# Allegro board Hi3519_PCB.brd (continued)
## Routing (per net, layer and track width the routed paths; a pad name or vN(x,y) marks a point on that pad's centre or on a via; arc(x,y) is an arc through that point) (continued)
AVDD33_AC: length 2.1
  TOP w0.254: v1(93.05,46.89) 93.05,46.89 U3.V18
  BOTTOM w0.254: C23.2 LB9.2 93.39,47.23 v1(93.05,46.89)
AVDD33_PLL: length 2
  TOP w0.254: U3.M5 v1(84.6,50.14)
  BOTTOM w0.254: v1(84.6,50.14) 84.6,50.5 C46.1 84.93,50.62 LB8.1
AVDD33_USB2: length 1.9
  TOP w0.254: U3.G18 92.72,53.71 v1(93.05,53.39)
  BOTTOM w0.254: C777.1 93.05,53.85 v1(93.05,53.39) 92.9,53.24 LB100.1
AVDD33_VDAC: length 1.9
  TOP w0.254: v1(91.75,46.24) 91.75,46.24 92.07,46.56 U3.V17
  BOTTOM w0.254: C48.1 92.17,45.82 v1(91.75,46.24) 91.17,46.24 LB10.1
AVDD_1.05V: length 7.9
  TOP w0.203: v2(127.59,72.33) 127.54,72.33 127.5,72.37 U2.40 ; U2.3 v2(124.56,77.07) ; U2.9 v2(122.16,77.07)
  BOTTOM w0.305: C64.1 122.98,76.37 ; C64.1 121.94,76.37 ; C64.1 122.46,76.89 ; C62.1 123.98,76.89 ; C62.1 124.5,76.37 ; C62.1 123.46,76.37 ; C63.1 129.11,73.18 ; C63.1 128.59,72.66 ; C63.1 129.11,72.14
AVDD_3V3_PHY: length 3.1
  TOP w0.203: U2.6 v2(123.36,77.76) ; v2(126.85,72.91) 126.71,72.77 U2.41
  BOTTOM w0.381: C56.1 126.95,73.01 v2(126.85,72.91)
  vias: v2(123.87,78.46)
AVDD_DDRPLL: length 7.4
  TOP w0.254: U3.E11 v1(88.5,54.69) ; U3.J5 v1(84.6,52.09)
  BOTTOM w0.254: v1(84.6,52.09) 85.18,52.09 LB6.2 85.76,51.51 C801.1 86.03,51.52 86.03,52.85 86.59,53.41 86.59,53.87 86.85,54.12 87.28,54.12 C800.1 87.85,54.69 v1(88.5,54.69)
AVDD_PLL: length 2.1
  TOP w0.254: U3.N8 v1(86.55,49.49)
  BOTTOM w0.254: LB7.1 C45.1 86.61,49.43 v1(86.55,49.49)
DDRIO_1.5V/1.35V: length 92.8
  TOP w0.254: C157.1 76.23,72.15 76.7,71.68 U14.N1 ; U14.C9 84.74,64.28 C162.1 ; U14.H9 80.7,63.26 81.18,62.78 C167.1 ; C164.1 75.16,62.32 76.7,63.86 U14.N9 ; U3.E13 v1(89.15,54.69) U3.E12 ; U14.R1 75.1,71.77 74.59,72.28 74.59,73.25 C166.1 ; U14.A1 C165.1 ; C270.1 86.9,62.88 87.28,63.26 87.28,64.14 U14.A8 ; U3.E6 v1(85.25,54.69) U3.E7 ; C34.1 83.32,64.1 U14.E9
  TOP w0.305: v1(84.3,64.72) U14.D9 ; U14.D2 v1(84.3,70.31) ; U14.G7 81.5,65.91 v1(81.1,65.51) ; U14.R9 75.1,63.53 74.58,63.01 74.07,63.01 73.69,62.63 C163.1 ; U14.B2 85.5,69.91 v1(85.9,69.51) ; U14.F1 v1(81.9,71.11) ; U14.C1 v1(84.3,71.11) ; U14.K2 v1(79.5,70.31) ; U14.H2 v1(81.1,69.51) ; U14.K8 v1(79.5,64.72)
  TOP w0.381: C270.1 87.58,61.76 v2(87.69,61.86) ; C34.1 83.9,61.76 v2(84,61.86) 84.1,61.76 C162.1 ; v2(74.48,61.86) 74.58,61.76 C164.1 ; C167.1 v2(81.84,61.76) ; C225.1 v2(85.63,72.53) ; v2(84.74,74.31) 84.64,74.21 C155.1 R176.2 ; R174.2 C154.1 v2(79.23,60.21) ; C165.1 v2(88.52,69.99) ; C157.1 v2(75.37,73.27) ; v2(72.95,61.86) 73.06,61.76 C163.1 ; C166.1 v2(73.72,73.27)
  BOTTOM w0.254: U14.C9 84.7,61.8 C162.1 ; U14.N1 76.7,71.68 76.23,72.15 C157.1 v2(75.37,73.27) ; C164.1 75.16,62.07 76.7,63.61 U14.N9 ; C271.1 86.64,62.63 86.3,62.97 U15.A1 ; C148.1 89.43,54.97 v1(89.15,54.69) ; v2(82.07,72.4) 80.7,71.03 U15.H9 ; C163.1 73.69,62.31 75.1,63.72 U14.R9 ; U14.R1 75.1,72.39 74.58,72.91 C166.1 ; C101.1 82.71,63.13 82.35,63.49 82.35,64.26 U15.F1
  BOTTOM w0.305: U15.D2 v1(84.3,64.72) ; U14.K8 v1(79.5,64.72) ; v1(81.1,69.51) 81.5,69.12 U15.G7 ; U15.B2 v1(85.9,65.51) ; U15.E9 83.6,71.21 83.6,71.77 83.98,72.15 C174.1 ; U15.H2 v1(81.1,65.51) ; U14.C1 v1(84.3,70.31) ; v2(85.63,72.53) 84.36,71.26 84.36,71.17 v1(84.3,71.11) U15.D9 ; U14.K2 v1(79.5,70.31) ; U15.A8 v1(85.9,69.51)
  BOTTOM w0.381: v2(65.31,63.64) 64.17,63.64 63.91,63.9 R31.2 ; C166.1 v2(73.72,73.27) ; C174.1 v2(84.71,73.27) ; v2(78.21,60.16) R174.2 C160.1 ; C101.1 v2(81.84,61.76) ; v2(74.48,61.86) 74.58,61.76 C164.1 ; C162.1 84.1,61.76 v2(84,61.86) ; v2(72.95,61.86) 73.06,61.76 C163.1 ; v2(82.07,72.4) 82.33,72.66 C168.1 ; C271.1 85.98,61.76 v2(85.91,61.84) ; C225.1 v2(85.63,72.53) ; C158.1 R181.2 v2(79.28,74.74)
  vias: v1(84.66,53.97) v1(84.61,53.39) v2(65.31,64.66) v2(66.45,64.66) v2(66.45,63.64)
DVDD_1.05V: length 5
  TOP w0.203: U2.36 125.36,69.55 v2(125.51,69.41) ; U2.28 122.16,69.57 v2(121.95,69.36)
  BOTTOM w0.305: 122.47,68.62 C60.1 121.95,69.14 ; C61.1 125.39,68.62 ; C61.1 124.87,69.14 ; C61.1 124.35,68.62
GND: length 628
  TOP w0.203: J1.31 v2(60.98,44.2) ; J1.74 v2(56.04,52.6) ; J1.43 v2(60.98,46.6) ; J1.67 v2(60.98,51.4) ; J1.46 v2(56.04,47) ; J1.22 56.24,42.2 56.04,42.4 v2(56.04,42.43) ; J1.37 v2(60.98,45.4) ; J1.13 v2(60.98,40.6) ; J1.61 v2(60.98,50.2) ; J1.55 v2(60.98,49) ; J1.7 v2(60.98,39.4) ; v2(56.04,39.8) J1.10 ; 100.11,46.32 99.93,46.5 97.92,46.5 97.4,47.02 95.85,47.02 v1(95.84,47.03) ; J1.85 v2(60.98,55) ; J1.1 v2(60.98,38.2) ; J1.79 v2(60.98,53.8) ; J1.49 v2(60.98,47.8) ; J1.25 v2(60.98,43) ; J1.28 v2(56.04,43.4) ; J1.52 v2(56.04,48.2) ; J1.40 v2(56.04,45.8) ; J1.62 v2(56.04,50.2) ; J1.19 v2(60.98,41.8) ; J1.34 v2(56.04,44.6) ; J1.73 v2(60.98,52.6)
  TOP w0.254: U3.L5 84.27,51.11 v1(84.6,51.44) U3.K5 ; U3.E4 v1(83.95,55.34) ; v1(96.04,51.83) 95.98,51.76 U3.K22 U3.K21 ; U3.AB22 95.64,43.65 v1(95.66,43.65) ; U3.Y20 v1(94.35,44.94) ; U14.B1 85.5,70.72 v1(85.9,71.12) ; 155.59,51.18 J28.8 v2(152.22,51.18) ; U3.N18 v1(93.05,50.14) ; J28.5 v2(152.22,52.68) ; U3.P21 v1(94.35,48.84) ; v1(91.75,46.89) U3.V16 ; U3.G4 v1(83.95,53.39) ; U3.N2 U3.N1 v1(80.55,49.81) ; v1(96.12,53.63) 96.04,53.71 U3.G22 U3.G21 ; U3.B16 v1(91.75,57.29) ; v1(83.3,49.49) 82.97,49.16 U3.P3 ; U7.13 63.76,26.66 v2(63.53,26.43) ; v1(93.7,53.39) 94.02,53.06 U3.H20 ; U3.K10 v1(87.85,52.09) U3.J11 ; U2.47 125.35,75.17 ; v1(87.85,46.24) 87.52,45.91 U3.W10 87.36,45.75 87.36,45.43 U3.Y10 ; U3.A22 v1(95.65,57.94) ; U22.63 v2(140.98,51.3) ; v1(86.55,54.69) U3.E8 U3.D7 ; U3.AB14 90.12,43.45 v1(90.15,43.42) ; U3.D19 v1(93.7,55.99) 93.37,56.31 U3.C19 ; v1(85.9,46.24) 85.57,45.92 U3.W7 85.45,45.79 85.45,45.39 U3.Y7 ; v1(82,44.29) 81.67,43.97 81.67,43.96 U3.AB1 ; v1(90.78,54.9) 90.76,54.88 90.26,54.88 U3.E14 ; U3.K18 v1(92.4,51.44) ; U3.E10 v1(87.2,54.69) U3.E9 ; U3.W20 v1(93.7,46.24) 93.37,45.92 U3.W19 ; U3.M8 v1(86.55,50.14) 86.87,49.81 U3.N9 ; 155.54,54.18 J28.2 v2(152.22,54.18) ; U3.L9 87.2,51.44 87.52,51.11 U3.L10 v1(87.85,51.44) 88.17,51.11 U3.L11 ; U3.K3 v1(82.65,51.44) ; U3.V8 86.22,46.56 v1(86.55,46.89) ; U3.U2 v1(82.65,47.54) ; v2(152.22,46.68) J28.17 155.59,46.68 ; U3.N5 v1(83.95,50.14) U3.M4 ; U3.B6 84.92,56.96 v1(84.6,57.29) U3.A6 ; v1(88.5,52.09) 88.5,52.09 U3.J12 U3.H12 ; v1(89.8,50.14) U3.M13 ; U3.J10 U3.H9 ; U3.A2 82.32,58.04 v1(82.09,58.28) 81.67,57.87 U3.A1 ; U3.E20 v1(94.35,55.34) ; U3.N14 v1(90.45,50.14) ; U3.B13 U3.A13 89.47,58.08 v1(89.52,58.12) ; U22.43 v2(133.72,48.66) ; U3.R10 v1(87.85,48.19) ; v2(152.22,49.68) J28.11 155.59,49.68 ; U7.36 85.78,26.66 v2(85.88,26.56) ; U3.G19 U3.F20 v1(94.35,54.04) ; U3.V4 v1(83.3,46.24) ; U3.K19 v1(93.7,52.09) ; U14.B3 v1(85.9,68.71) ; U3.K13 v1(89.15,52.09) ; U3.U21 v1(95,46.89) ; U3.N13 v1(89.8,49.49) ; U3.L8 v1(86.55,50.79) ; U22.57 v2(141.25,48.3) ; U3.M20 v1(94.35,50.79) ; v2(64.17,16.27) 64.42,16.53 U20.11 ; U3.C11 v1(88.5,56.64)
  TOP w0.305: C79.1 148.63,41.52 ; C79.1 148.11,41 ; C79.1 147.59,41.52 ; 79.51,79.76 C86.2 ; C86.2 79.51,80.8 ; C86.2 78.99,80.28 ; R50.1 91.82,85.4 ; R50.1 92.34,84.88 ; R50.1 91.3,84.88 ; R137.1 70.66,18.79 ; R137.1 69.61,18.79 ; R137.1 70.13,18.26 ; 105.85,72.27 C53.2 ; C53.2 106.37,72.79 ; C53.2 105.85,73.31 ; R44.1 98.81,85.4 ; R44.1 99.33,84.88 ; R44.1 98.29,84.88 ; U14.D1 v1(83.5,70.31) U14.E2 ; C58.2 106.37,69.79 ; C58.2 105.85,69.27 ; C58.2 105.85,70.31 ; 97.04,84.88 R46.1 ; R46.1 97.56,85.4 ; R46.1 98.08,84.88 ; 134.84,9.29 J4.1 ; J4.1 136.05,8.08 ; J4.1 136.05,10.49 ; J4.1 137.25,9.29 ; 108.85,77.32 C266.2 ; C266.2 109.37,77.84 ; C266.2 108.33,77.84 ; 78.06,52.34 R113.1 78.75,52.95 ; J28.23 162.4,57.43 ; J28.23 160.73,58.51 ; J28.23 160.73,56.35 ; J28.23 159.05,57.43 ; 160.73,41.85 J28.22 ; J28.22 160.73,44.01 ; J28.22 162.4,42.93 ; J28.22 159.05,42.93 ; C163.2 74.21,60.95 ; C163.2 73.17,60.95 ; C163.2 73.69,60.43 ; v2(60.74,23.66) R89.1 61.47,23.14 ; C209.2 132.43,11.88 ; C209.2 131.09,13.22 ; C209.2 131.09,10.55 ; C209.2 129.76,11.88 ; 75.16,60.43 C164.2 74.64,60.95 ; 113.89,25.41 J2.1 ; J2.1 115.09,26.62 ; J2.1 116.3,25.41 ; J2.1 115.09,24.21 ; 153.22,18.48 J16.3 ; J16.3 155.32,17.25 ; J16.3 155.32,19.71 ; J16.3 157.41,18.48 ; v1(85.25,63.77) 85.5,64.02 U14.B9 ; 108.75,73.29 C265.2 ; C265.2 109.28,72.77 ; C265.2 109.28,73.82 ; 68.93,71.77 J5.1 ; J5.1 71.34,71.77 ; J5.1 70.13,70.56 ; J5.1 70.13,72.98 ; 77.2,60.43 R175.1 ; 146.97,41 R68.1 ; R68.1 146.45,41.52 ; R68.1 147.49,41.52 ; 105.85,68.89 C40.2 106.37,68.37 ; U14.F9 v1(81.9,63.92) U14.G9 ; C35.2 61.6,73.94 ; C35.2 61.08,73.42 ; C35.2 61.6,72.9 ; C246.2 106.37,76.79 ; C246.2 105.85,77.31 ; C246.2 105.85,76.27 ; 90.68,24 C38.2 ; C38.2 90.68,25.05 ; C38.2 90.16,24.53 ; 97.76,8.4 J25.4 ; J25.4 98.46,9.29 ; J25.4 97.76,10.18 ; J3.1 57.88,25.03 ; J3.1 56.67,26.24 ; J3.1 56.67,23.83 ; J3.1 55.47,25.03 ; 75.71,74.08 C157.2 ; C157.2 76.75,74.08 ; C157.2 76.23,74.6 ; U14.D8 v1(83.5,64.71) U14.E8 ; 77.65,79.76 R182.2 ; R182.2 78.17,80.28 ; R182.2 77.65,80.8 ; 154.07,80.09 J20.11 155.47,81.49 ; 134.51,43.55 C71.2 ; C71.2 135.03,43.03 ; C71.2 135.55,43.55 ; C2.2 74.07,56.44 ; C2.2 73.55,55.92 ; C2.2 74.59,55.92 ; C47.2 97.02,41.42 ; 74.07,52.81 C3.2 73.55,53.33 ; 108.33,68.37 C24.2 ; C24.2 108.85,68.89 ; C24.2 109.37,68.37 ; 101.38,8.4 J50.1 ; J50.1 100.68,9.29 ; J50.1 101.38,10.18 ; C193.1 v2(100.23,42.94) ; U14.T9 v1(74.3,63.77) ; 86.89,10.43 J21.8 86.89,8.65 ; 94.54,84.88 R42.1 ; R42.1 95.06,85.4 ; R42.1 95.58,84.88 ; U14.T1 v1(74.3,71.32) ; R47.1 88.59,84.88 ; R47.1 87.55,84.88 ; R47.1 88.07,85.4 ; 88.8,84.88 R48.1 ; R48.1 89.84,84.88 ; R48.1 89.32,85.4 ; C165.2 89.34,71.24 ; C165.2 89.86,70.71 ; C165.2 89.34,70.19 ; 102.18,53.35 R94.2 101.66,53.88 ; J26.1 66.01,84.09 ; J26.1 65.31,84.98 ; J26.1 65.31,83.2 ; C190.1 v2(100.23,43.96) ; C219.2 75.23,51.22 ; C219.2 74.71,51.74 ; C219.2 74.19,51.22 ; R177.1 81.82,74.73 ; 154.07,63.96 J20.12 155.47,62.56 ; 80.24,60.43 R114.1 ; U14.M1 77.25,70.97 v1(77.25,71.26) ; 80.8,74.73 C156.2 80.28,74.21 ; v1(86.77,63.9) 86.72,63.9 U14.A9 ; 96.54,36.96 R98.1 97.06,37.48 ; 152.8,57.43 J28.21 ; J28.21 154.77,58.51 ; J28.21 154.77,56.35 ; J28.21 156.73,57.43 ; 154.77,41.85 J28.20 ; J28.20 156.73,42.93 ; J28.20 154.77,44.01 ; J28.20 152.8,42.93 ; U14.G1 81.5,70.71 v1(81.9,70.32) ; C166.2 74.58,74.6 ; C166.2 75.1,74.08 ; C166.2 74.06,74.08 ; 158.22,11.36 J16.1 ; J16.1 156.98,13.58 ; J16.1 158.22,15.8 ; R49.1 91.09,84.88 ; R49.1 90.57,85.4 ; R49.1 90.05,84.88 ; R45.1 96.83,84.88 ; R45.1 95.79,84.88 ; R45.1 96.31,85.4 ; 81.7,60.95 C167.2 81.18,60.43 ; U14.E1 v1(82.7,71.11) ; U14.J8 v1(80.3,65.51) ; U14.J2 v1(80.3,70.32) ; C235.2 105.85,78.64 ; C235.2 106.37,78.12 ; C235.2 105.85,77.6 ; U14.P1 v1(75.9,71.31) ; U14.M9 v1(77.9,63.92) ; U14.P9 v1(75.9,63.77) ; 76.18,60.43 C153.2 ; U14.G8 v1(81.9,64.72)
  TOP w0.356: v2(146.59,49.85) 146.64,49.8 U12.3 U12.8 v2(149.53,49.8) ; v2(149.53,52.97) U11.8 U11.3 v2(146.59,52.97) ; R245.1 v2(89.62,18.81) ; v2(110.99,15.73) 110.92,15.8 U23.4 ; R81.2 v2(115.19,15.79)
  TOP w0.381: OSC1.2 131.35,66.18 v2(130.71,66.82) ; R143.2 125.79,67.88 v2(125.86,67.81) ; C4.2 138.8,42.88 v2(138.84,42.84) ; U16.10 v2(71.38,23.76) ; C213.2 v2(118.78,68.98) ; U13.1 v2(93.31,31.57) ; C227.2 v2(93.31,33.92) ; C270.2 v2(87.69,60.95) ; J12.11 148.53,38.08 v2(148.24,38.37) ; v2(143.67,27.32) 143.79,27.32 144.43,27.95 C247.2 ; J16.1 159.65,13.58 ; C155.2 83.85,73.04 v2(83.34,72.53) ; R38.2 v2(141.64,44.06) ; R151.2 v2(141.76,57.67) ; C154.2 v2(79.23,62.55) ; Q3.2 v2(139.35,25.54) ; C225.2 v2(85.63,75.71) ; 130.33,69.48 v2(130.33,70.37) ; X1.2 73.65,51.53 v2(74.33,52.21) ; C83.2 147.25,28.44 v2(147.6,28.08) ; J12.10 v2(150.12,22.14) ; U17.2 v2(147.99,45.1) ; X1.4 v2(70.6,49.33) ; R141.2 117.86,78.45 v2(117.85,78.46) ; R214.2 142.93,48.27 v2(143.21,48.27) ; R70.2 143.16,27.95 v2(142.65,27.45) ; C124.1 v2(61.94,19.57) ; C162.2 v2(83.98,60.95) C34.2 ; v2(96.42,42.18) 96.58,42.03 C47.2 ; R91.2 v2(98.07,38.75) ; R35.2 v2(144.05,57.67) ; J12.6 v2(151.03,27.98) ; R39.2 v2(145.19,57.67) ; C65.2 v2(126.88,70.17) ; v2(98.28,40.15) C228.2 ; v2(157.89,38.98) J12.13 v2(161.55,38.98) ; R55.2 v2(143.95,23.51) ; v2(77.42,47.11) 77.53,47 R93.2 ; U13.3 v2(93.18,29.67)
  TOP w0.508: J18.12 121.6,58.6 v2(121.25,58.24) ; v2(120.07,60.45) 119.82,60.2 J18.7 ; J18.72 v2(120.55,34.6) ; J18.68 v2(120.55,36.2) ; J18.76 v2(120.55,33) ; J18.80 v2(120.55,31.4)
  GND02 w0.305: 158.22,11.36 J16.1 ; J16.1 159.45,13.58 ; J16.1 156.98,13.58 ; J16.1 158.22,15.8 ; J25.4 97.76,10.18 ; J25.4 98.46,9.29 ; J25.4 97.76,8.4 ; 134.84,9.29 J4.1 ; J4.1 137.25,9.29 ; J4.1 136.05,10.49 ; J4.1 136.05,8.08 ; J50.1 101.38,10.18 ; J50.1 101.38,8.4 ; J50.1 100.68,9.29 ; 160.73,41.85 J28.22 ; J28.22 160.73,44.01 ; J28.22 162.4,42.93 ; J28.22 159.05,42.93 ; 129.76,11.88 C209.2 ; C209.2 131.09,10.55 ; C209.2 132.43,11.88 ; C209.2 131.09,13.22 ; 152.8,57.43 J28.21 ; J28.21 154.77,56.35 ; J28.21 156.73,57.43 ; J28.21 154.77,58.51 ; J28.23 160.73,58.51 ; J28.23 160.73,56.35 ; J28.23 159.05,57.43 ; J28.23 162.4,57.43 ; 152.8,42.93 J28.20 ; J28.20 156.73,42.93 ; J28.20 154.77,44.01 ; J28.20 154.77,41.85 ; 154.07,80.09 J20.11 155.47,81.49 ; J5.1 71.34,71.77 ; J5.1 70.13,70.56 ; J5.1 70.13,72.98 ; J5.1 68.93,71.77 ; 153.22,18.48 J16.3 ; J16.3 157.41,18.48 ; J16.3 155.32,19.71 ; J16.3 155.32,17.25 ; J21.8 87.58,9.54 ; J21.8 86.89,10.43 ; J21.8 86.89,8.65 ; 154.07,63.96 J20.12 155.47,62.56 ; 113.89,25.41 J2.1 ; J2.1 115.09,26.62 ; J2.1 116.3,25.41 ; J2.1 115.09,24.21 ; 56.67,23.83 J3.1 ; J3.1 56.67,26.24 ; J3.1 57.88,25.03 ; J3.1 55.47,25.03 ; J26.1 66.01,84.09 ; J26.1 65.31,83.2 ; J26.1 65.31,84.98
  ART03 w0.762: J20.13 149.75,78.89 146.21,82.44
  BOTTOM w0.254: C42.2 92.14,52.78 v1(92.23,52.69) 92.23,52.19 C41.2 ; C23.1 95.33,47.54 v1(95.84,47.03) ; U10.24 107.35,77.62 107.22,77.48 ; U10.49 109.35,68.24 109.12,68.47 ; v1(96.04,55.01) 95.41,54.37 R34.1 ; C39.2 83.46,52.9 v1(83.95,53.39) ; 109.12,77.36 109.35,77.58 U10.28 ; v1(87.2,48.84) 86.48,48.84 C189.2 ; U10.13 105.99,74.29 ; v1(91.75,46.89) 91.87,46.76 C48.2 ; C176.2 85.07,47.07 v1(84.6,47.54) 84.89,47.84 C20.2 ; U10.21 105.85,77.58 106.08,77.36 ; U10.44 109.21,70.29 ; U10.16 105.99,75.79 ; v1(88.5,55.34) 88.23,55.61 C800.2 ; C45.2 88.08,49.07 v1(87.85,48.84) ; v1(94.35,54.04) 94.3,54.09 C777.2 ; C145.2 85.86,55.38 v1(86.55,54.69) 86.55,54.38 86.13,53.96 C146.2 ; v1(83.95,50.14) 83.89,50.2 C46.2 ; U10.9 105.99,72.29 ; C147.2 84.06,55.45 v1(83.95,55.34) ; 106.08,68.59 105.77,68.29 U10.1 ; U10.53 107.35,68.43 ; R558.1 89.46,58.07 v1(89.52,58.12) ; U10.39 109.21,72.79 ; v1(88.5,51.44) 88.59,51.35 C188.2 ; U10.6 105.99,70.79 ; v1(86.55,52.09) 86.55,51.95 C801.2 ; v1(90.34,54.4) 89.97,54.03 C148.2 ; U10.55 106.35,68.43 ; U10.33 109.26,75.79
  BOTTOM w0.305: 149.75,49.82 C109.2 ; C109.2 150.27,50.35 ; C109.2 150.79,49.82 ; U14.M9 v1(77.9,63.92) ; U14.G1 81.5,70.71 v1(81.9,70.32) U15.G8 ; J25.4 98.46,9.29 ; J25.4 97.76,8.4 ; J25.4 97.76,10.18 ; C105.2 131.5,41.3 ; C105.2 131.5,40.26 ; C105.2 132.02,40.78 ; 158.22,11.36 J16.1 ; J16.1 156.98,13.58 ; J16.1 158.22,15.8 ; J16.1 159.45,13.58 ; C91.2 122.05,57.31 ; C91.2 122.05,56.26 ; C91.2 121.53,56.78 ; C76.2 131.6,49.08 ; C76.2 132.12,48.55 ; C76.2 131.08,48.55 ; 122.47,67.81 C60.2 121.95,67.29 ; 87.6,46.84 C177.2 86.6,46.84 v1(86.55,46.89) ; 56.67,23.83 J3.1 ; J3.1 57.88,25.03 ; J3.1 56.67,26.24 ; J3.1 55.47,25.03 ; J21.8 87.58,9.54 ; J21.8 86.89,10.43 ; J21.8 86.89,8.65 ; 137.05,53.71 C75.2 ; C75.2 138.09,53.71 ; C75.2 137.57,53.19 ; 121.21,75.19 C55.2 121.74,75.71 ; 99.2,27.68 C36.2 ; C36.2 100.25,27.68 ; C36.2 99.73,27.15 ; U14.E2 v1(83.5,70.31) U15.D8 ; 139.07,49.79 C68.2 ; C68.2 138.55,50.31 ; C68.2 139.07,50.83 ; U14.T1 v1(74.3,71.32) ; 73.69,60.43 C163.2 ; C163.2 73.17,60.95 ; C163.2 74.21,60.95 ; 82.21,51.17 C44.2 81.82,50.73 ; 83.98,74.6 C174.2 83.46,74.08 ; 81.3,84.88 R109.2 81.82,85.4 ; v1(85.25,63.77) 85.5,64.02 U14.B9 ; 120.83,71.88 C59.2 ; C59.2 121.35,72.4 ; C59.2 120.83,72.93 ; 130.56,61.09 C77.2 ; C77.2 131.08,61.61 ; C77.2 130.56,62.13 ; J2.1 116.3,25.41 ; J2.1 115.09,24.21 ; J2.1 115.09,26.62 ; J2.1 113.89,25.41 ; C78.2 135.93,44.13 ; C78.2 135.41,43.61 ; C78.2 134.89,44.13 ; 155.47,81.49 J20.11 154.07,80.09 ; C66.2 136.21,76.5 ; C66.2 135.69,77.02 ; C66.2 135.69,75.98 ; 74.06,74.08 C166.2 ; C166.2 75.1,74.08 ; C166.2 74.58,74.6 ; C118.2 126.9,47.04 ; C118.2 126.38,46.52 ; C118.2 127.42,46.52 ; U14.J2 v1(80.3,70.32) ; 124.45,71.64 C57.2 124.97,72.16 ; 119.96,51.96 C92.2 119.44,51.44 ; 159.05,57.43 J28.23 ; J28.23 160.73,56.35 ; J28.23 160.73,58.51 ; J28.23 162.4,57.43 ; J28.21 156.73,57.43 ; J28.21 154.77,58.51 ; J28.21 154.77,56.35 ; J28.21 152.8,57.43 ; 75.16,60.43 C164.2 ; C164.2 74.64,60.95 ; C164.2 75.68,60.95 ; 88.57,46.88 C151.2 ; C151.2 88.97,47.32 ; C151.2 88.97,46.43 ; C88.2 61.98,24.12 ; C88.2 61.98,23.08 ; C88.2 61.45,23.6 ; 100.68,9.29 J50.1 ; J50.1 101.38,10.18 ; J50.1 101.38,8.4 ; J5.1 71.34,71.77 ; J5.1 70.13,72.98 ; J5.1 68.93,71.77 ; J5.1 70.13,70.56 ; 94.54,49 R92.2 94.99,49.44 ; U15.E1 v1(83.5,64.71) ; v1(83.5,64.71) U15.D1 ; v1(83.5,64.71) U14.E8 ; 61.19,70.23 C13.2 ; C13.2 60.67,70.75 ; C13.2 61.19,71.28 ; 84.47,26.66 C50.2 ; C50.2 85.51,26.66 ; C50.2 84.99,26.14 ; U14.J8 v1(80.3,65.51) ; C52.2 79.95,32.65 ; C52.2 79.43,33.18 ; C52.2 79.43,32.13 ; U15.A9 86.3,70.72 v1(85.9,71.12) 85.5,70.72 U14.B1 ; U15.F9 v1(82.7,71.11) ; 88.97,47.52 C22.2 88.57,47.97 ; 136.29,48.55 C69.2 ; C69.2 136.81,49.08 ; C69.2 137.33,48.55 ; R168.2 69.44,84.85 ; R168.2 68.92,84.33 ; R168.2 68.92,85.37 ; 111.1,30.48 C14.2 ; C14.2 111.63,31 ; C14.2 111.1,31.52 ; R180.1 78.26,74.6 ; 83.01,46.88 C150.2 83.41,46.43 ; 128.4,47.63 C106.2 ; C106.2 127.88,48.15 ; C106.2 128.4,48.67 ; C67.2 139.07,53.32 ; C67.2 138.55,52.8 ; C67.2 139.07,52.28 ; C64.2 122.98,75.55 ; C64.2 122.46,75.03 ; C64.2 121.94,75.55 ; 75.71,74.08 C157.2 76.23,74.6 ; 160.73,41.85 J28.22 ; J28.22 159.05,42.93 ; J28.22 162.4,42.93 ; J28.22 160.73,44.01 ; 131.09,10.55 C209.2 ; C209.2 129.76,11.88 ; C209.2 131.09,13.22 ; C209.2 132.43,11.88 ; 86.12,26.66 C51.2 ; C51.2 87.17,26.66 ; C51.2 86.64,26.14 ; 82.33,74.6 C168.2 82.85,74.08 ; C19.2 88.35,47.61 ; C19.2 87.95,47.16 ; C19.2 87.95,48.06 ; 93.82,54.69 C149.2 ; C149.2 93.82,55.58 ; C149.2 94.22,55.13 ; 154.77,41.85 J28.20 ; J28.20 154.77,44.01 ; J28.20 156.73,42.93 ; J28.20 152.8,42.93 ; C80.2 139.58,43.34 ; C80.2 139.58,42.29 ; C80.2 139.06,42.81 ; 110.23,49.54 C37.2 110.75,49.02 ; 83.38,49.23 C175.2 82.98,48.78 ; C74.2 134.28,53.71 ; C74.2 133.76,53.19 ; C74.2 133.24,53.71 ; J16.3 155.32,19.71 ; J16.3 153.22,18.48 ; J16.3 157.41,18.48 ; J16.3 155.32,17.25 ; 104.3,44.1 C16.2 ; C16.2 103.78,44.62 ; C16.2 104.82,44.62 ; 91.81,11.19 C81.2 ; C81.2 92.33,10.67 ; C81.2 92.33,11.71 ; 94.34,51.45 C152.2 93.95,51.9 ; 124.35,67.81 C61.2 124.87,67.29 ; 155.47,62.56 J20.12 154.07,63.96 ; U14.T9 v1(74.3,63.77) ; 95.56,26.93 C17.2 ; C17.2 95.56,27.97 ; C17.2 96.08,27.45 ; C159.2 77.25,74.6 ; 74.94,9.02 C82.2 ; C82.2 74.94,10.06 ; C82.2 74.41,9.54 ; 132.99,38.75 R56.2 ; R56.2 133.51,39.27 ; R56.2 134.03,38.75 ; U15.B3 v1(85.9,66.32) ; U14.P1 v1(75.9,71.31) ; 133.25,43.61 C70.2 132.73,44.13 ; 74.29,30.24 C212.1 ; C212.1 74.81,30.76 ; C212.1 74.81,29.72 ; J4.1 136.05,10.49 ; J4.1 136.05,8.08 ; J4.1 137.25,9.29 ; J4.1 134.84,9.29 ; 123.98,75.03 C62.2 ; C62.2 124.5,75.55 ; C62.2 123.46,75.55 ; U14.M1 77.25,70.97 v1(77.25,71.26) ; U14.P9 v1(75.9,63.77) ; R115.1 81.31,74.6 ; C90.2 57.45,59.1 ; C90.2 56.93,59.62 ; C90.2 56.41,59.1 ; 119.96,52.97 C89.2 119.44,53.5 ; C72.2 138.21,59.87 ; U14.G9 v1(81.9,64.72)
  BOTTOM w0.356: R103.1 v2(122.23,26.28)
  BOTTOM w0.381: v2(151.27,38.98) J13.10 150.12,40.1 v2(150.22,40.2) ; C233.2 v2(127.16,77.99) ; C73.2 v2(128.17,52.97) ; v2(147.83,34.13) 147.83,33.87 147.4,33.44 C84.2 ; R108.2 v2(72.42,81.29) ; v2(77.63,62.5) 77.2,62.07 C160.2 ; v2(81.84,60.9) 81.89,60.95 C101.2 ; R244.2 v2(68.99,13.35) ; v2(157.89,38.98) J12.13 v2(161.55,38.98) ; C242.2 127.28,55.77 v2(127.18,55.67) ; R243.2 v2(60.48,13.35) ; C15.2 v2(111.03,43.07) ; R253.1 v2(65.31,74.18) ; C1.2 v2(80.32,75.99) ; R252.2 v2(129.19,71.01) ; C271.2 v2(85.91,60.95) ; v2(105.06,46.5) 105.31,46.75 R12.2 ; J13.11 v2(151.27,24.38) ; R167.2 v2(66.83,79.14) ; C237.2 126.33,67.39 125.91,67.81 v2(125.86,67.81) ; C229.2 63.85,26.11 v2(63.53,26.43) ; R71.2 143.29,33.44 143.5,33.23 v2(143.67,33.23) 144.06,33.23 C248.2 ; C158.2 v1(80.29,72.53) ; 85.88,82.56 v2(85.88,83.33) ; C221.2 v2(69.37,80.91) ; C56.2 v2(127.54,74.56) ; 83.85,82.56 v2(83.85,83.33) R40.2 ; v2(80.22,59.83) 80.24,59.86 R114.1 R178.1 ; R232.2 v2(107.56,30.83) ; v2(161.68,23.48) J12.9 157.93,23.48 v2(157.9,23.51) ; R187.1 v2(66.71,74.18) ; R129.1 v2(96.42,42.18) ; C225.2 v2(85.63,75.71) ; C220.2 v2(69.37,83.58) ; Q4.2 139.22,37.86 v2(139.35,37.86) ; U19.4 v2(75.98,84.09) ; C63.2 v2(130.59,72.66) ; C162.2 v2(83.98,60.95)
  BOTTOM w0.508: v2(89.13,16.4) 89.13,16.39 U25.2 ; J13.6 v2(151.11,34.48)
  vias: v1(78.14,48.53) v1(78.77,49.81) v1(87.2,52.09) v1(87.84,53.48) v1(89.32,53.84) v1(89.31,47.39) v1(89.8,51.44) v1(91.72,48.55) v1(97.26,54.96) v2(52.1,73.55) v2(52.1,69.74) v2(52.1,65.93) v2(52.1,62.12) v2(52.1,58.31) v2(52.1,54.5) v2(52.1,45.61) v2(52.1,41.8) v2(52.1,37.99) v2(52.1,34.18) v2(52.1,30.37) v2(52.1,26.56) v2(52.1,22.75) v2(52.1,12.97) v2(52.74,8.65) v2(53.12,52.59) v2(53.12,48.78) v2(53.12,19.45) v2(53.12,15.64) v2(53.4,60.16) v2(53.57,68.04) v2(53.62,36.11) v2(53.73,79.11) v2(53.8,76.16) v2(54.26,74.31) v2(54.26,30.88) v2(54.51,28.21) v2(55.12,70.65) v2(55.35,62.6) v2(55.71,17.92) v2(55.63,15.64) v2(55.78,20.97) v2(56.27,76.55) v2(56.29,73.4) v2(56.57,34) v2(56.62,67.66) v2(56.93,59.96) v2(57.31,7.84) v2(57.46,71.49) v2(57.43,28.59) v2(57.59,62.12) v2(57.84,79.21) v2(58.07,68.85) v2(58.45,86.12) v2(58.83,75.71) v2(58.83,74.44) v2(58.86,15) v2(58.98,62.09) v2(59.34,20.84) v2(59.34,19.7) v2(59.34,18.56) v2(59.47,31.51) v2(59.47,22.24) v2(59.59,9.67) v2(59.72,82.31) v2(59.97,27.57) v2(60.23,76.47) v2(60.23,68.59) v2(60.36,66.05) v2(60.38,62.09) v2(60.46,78.98) v2(60.48,70.75) v2(60.61,22.24) v2(60.71,33.21) v2(60.99,63.77) v2(60.99,56.28) v2(61.12,15.51) v2(61.37,11.83) v2(61.88,20.84) v2(62.26,86.12) v2(62.26,17.67) v2(62.39,80.41) v2(62.39,7.81) v2(62.9,68.85) v2(62.9,67.58) v2(62.9,66.31) v2(62.9,65.04) v2(63.23,33.21) v2(63.91,62.24) v2(64.19,53.66) v2(64.17,15.25) v2(64.37,71.54) v2(65.18,16.27) v2(65.18,15.25) v2(65.69,58.21) v2(65.94,77.87) v2(66.6,55.62) v2(66.71,19.95) v2(66.68,7.84) v2(67.47,67.32) v2(67.47,65.04) v2(67.47,62.5) v2(67.47,59.83) v2(67.59,70.47) v2(67.85,53.99) v2(67.85,11.06) v2(68.03,75.28) v2(68.23,86.12) v2(68.23,56.28) v2(68.23,14.87) v2(68.56,30.62) v2(68.89,9.01) v2(68.99,60.47) v2(68.99,24.53) v2(69.19,69.1) v2(69.12,26.94) v2(69.12,21.86) v2(69.12,18.18) v2(69.63,84.85) v2(69.98,77.03) v2(70.08,65.42) v2(70.24,55.51) v2(70.29,52.77) v2(70.29,50.89) v2(70.46,10.38) v2(70.57,62.85) v2(70.87,84.09) v2(71.35,60.29) v2(71.4,12.97) v2(71.66,57.42) v2(71.61,8.93) v2(71.86,74.69) v2(72.29,84.09) v2(72.7,71.77) v2(72.95,60.95) v2(73.13,47.61) v2(73.33,55.92) v2(73.4,53.33) v2(73.31,28.11) v2(73.31,26.84) v2(73.31,25.57) v2(73.31,10.17) v2(73.69,74.31) v2(73.69,33.21) v2(73.87,85.16) v2(73.94,30.24) v2(74.45,60.95) v2(74.58,28.11) v2(74.58,26.84) v2(74.58,25.57) v2(74.81,76.62) v2(74.96,10.68) v2(74.96,7.81) v2(75.11,47.61) v2(75.34,74.31) v2(75.6,51.22) v2(75.72,53.86) v2(75.85,28.11) v2(75.85,26.84) v2(75.85,25.57) v2(75.98,86.12) v2(76.18,60.14) v2(76.74,50.81) v2(77.25,74.74) v2(77.6,84.98) v2(77.63,51.96) v2(78.26,74.74) v2(78.52,80.28) v2(78.77,7.81) v2(79.79,86.12) v2(80.17,32.83) v2(80.8,74.94) v2(80.8,31.51) v2(81.82,85.61) v2(81.82,74.94) v2(82.58,7.81) v2(82.71,74.94) v2(83.6,86.12) v2(83.98,74.94) v2(84.36,14.49) v2(84.66,34.15) v2(85.32,77.94) v2(85.88,86.12) v2(85.88,28.97) v2(86.39,7.81) v2(86.64,18.05) v2(87.41,11.95) v2(87.53,72.61) v2(88.07,85.61) v2(88.55,24.91) v2(88.68,36.59) v2(89.32,85.61) v2(89.31,13.86) v2(89.44,69.99) v2(89.69,24.91) v2(90.2,7.81) v2(90.51,12.28) v2(90.57,85.61) v2(90.58,27.57) v2(90.71,23.51) v2(91.22,21.35) v2(91.72,70.63) v2(91.82,85.61) v2(92.11,11.95) v2(92.19,67.58) v2(92.19,65.04) v2(92.19,62.5) v2(92.49,21.35) v2(93.4,83.81) v2(94.01,7.81) v2(94.14,38.24) v2(94.26,21.35) v2(94.9,35.19) v2(94.87,13.65) v2(95.06,85.61) v2(95.66,36.29) v2(95.66,28.34) v2(96.17,32.02) v2(96.31,85.61) v2(96.68,21.1) v2(96.8,79.52) v2(97.11,35.07) v2(97.41,41.39) v2(97.41,36.26) v2(97.44,27.57) v2(97.56,85.61) v2(97.82,19.22) v2(97.82,7.81) v2(97.95,12.84) v2(98.58,27.57) v2(98.58,23.38) v2(98.81,85.61) v2(99.09,19.22) v2(99.14,36.29) v2(99.17,35.07) v2(99.85,23.38) v2(99.85,11.7) v2(100.03,39.94) v2(100.34,38.78) v2(100.36,19.19) v2(100.49,45.28) v2(100.49,27.7) v2(100.67,56.63) v2(100.74,77.36) v2(101.12,86.12) v2(101.12,23.38) v2(101.25,41.04) v2(101.63,19.22) v2(101.63,7.81) v2(101.88,27.7) v2(102.01,42.18) v2(102.39,23.38) v2(102.52,53.69) v2(102.54,31.26) v2(102.52,28.97) v2(102.65,30.24) v2(102.77,16.91) v2(103.1,37.61) v2(103.15,13.6) v2(103.28,28.08) v2(103.41,79.64) v2(103.54,20.08) v2(103.64,60.67) v2(103.66,22.37) v2(103.79,39.82) v2(103.94,24.04) v2(103.97,8.02) v2(104.04,11.83) v2(104.17,35.09) v2(104.48,36.26) v2(104.7,84.06) v2(104.68,38.75) v2(104.93,86.12) v2(105.29,30.65) v2(105.29,8.85) v2(105.82,41.04) v2(105.85,35.14) v2(105.92,60.84) v2(105.92,37.61) v2(106.08,42.05) v2(106.08,39.82) v2(106.15,59.32) v2(106.15,58.31) v2(106.15,56.91) v2(106.15,55.89) v2(106.2,43.07) v2(106.46,84.72) v2(106.89,36.29) v2(106.89,10.89) v2(106.96,76.85) v2(106.96,75.58) v2(106.96,74.31) v2(106.96,73.04) v2(106.96,71.77) v2(106.96,70.5) v2(106.96,69.23) v2(107.22,38.75) v2(107.6,85.99) v2(107.6,34.69) v2(108.23,76.85) v2(108.23,75.58) v2(108.23,74.31) v2(108.23,73.04) v2(108.23,71.77) v2(108.23,70.5) v2(108.23,69.23) v2(108.23,17.67) v2(108.23,16.4) v2(108.23,15.13) v2(108.23,13.86) v2(108.21,8.93) v2(108.36,53.48) v2(108.49,37.61) v2(108.59,43.07) v2(108.62,51.36) v2(108.62,49.27) v2(108.62,46.17) v2(109.28,85.16) v2(109.38,34.56) v2(109.5,12.33) v2(109.5,10.94) v2(109.63,49.27) v2(109.63,46.17) v2(109.76,38.75) v2(110.09,35.93) v2(110.22,59.32) v2(110.22,58.31) v2(110.22,56.91) v2(110.22,55.89) v2(110.39,42.05) v2(110.39,41.04) v2(110.39,39.89) v2(110.65,46.17) v2(110.9,53.48) v2(111.66,7.84) v2(111.79,85.1) v2(111.71,37.53) v2(111.79,35.83) v2(111.92,31) v2(112.04,33.92) v2(112.3,15.64) v2(112.55,41.62) v2(112.55,38.29) v2(113.04,26.89) v2(113.06,7.81) v2(113.26,28.64) v2(113.31,22.24) v2(113.44,39.08) v2(113.7,35.57) v2(114.08,41.67) v2(114.2,31.76) v2(114.33,23.26) v2(114.58,85.1) v2(114.58,36.34) v2(114.71,42.69) v2(114.76,39.49) v2(114.71,33.03) v2(114.84,37.68) v2(114.84,9.67) v2(115.09,13.86) v2(115.22,28.72) v2(115.6,81.55) v2(115.73,23.26) v2(116.36,42.48) v2(116.34,34.56) v2(116.34,32.91) v2(116.44,36.11) v2(116.59,31.36) v2(116.79,37.76) v2(116.9,39.41) v2(116.87,11.57) v2(116.87,7.81) v2(116.97,76.72) v2(116.94,41) v2(117.15,29.45) v2(117.12,23.26) v2(117.76,21.1) v2(119.03,15.64) v2(119.28,22.62) v2(119.39,39.4) v2(119.39,36.2) v2(119.39,34.6) v2(119.39,33) v2(119.39,31.4) v2(119.33,28.44) v2(119.44,42.41) v2(119.44,37.78) v2(119.54,51.07) v2(119.54,50.05) v2(119.59,26.38) v2(119.66,44.77) v2(120.05,56.91) v2(120.05,55.89) v2(120.11,58.24) v2(120.17,52.06) v2(120.66,21.17) v2(120.68,7.81) v2(120.81,41) v2(121.06,56.91) v2(121.06,55.89) v2(121.19,60.47) v2(121.16,51.65) v2(121.16,37.53) v2(121.34,43.4) v2(121.51,75.02) v2(121.95,72.4) v2(122.33,74.18) v2(122.59,71.64) v2(122.97,67.81) v2(123.16,74.64) v2(123.17,73.4) v2(123.65,36.13) v2(123.63,33.01) v2(123.63,30.6) v2(123.86,37.73) v2(123.98,48.78) v2(124.36,86.12) v2(124.43,74.64) v2(124.49,15.76) v2(124.49,7.81) v2(124.62,72.4) v2(124.97,39.18) v2(124.92,29.66) v2(125.13,83.33) v2(125.13,50.69) v2(125.3,36.34) v2(126.09,52.85) v2(126.24,46.52) v2(126.4,24.14) v2(126.37,22.62) v2(126.7,32.15) v2(126.78,35.32) v2(126.75,33.59) v2(126.8,30.22) v2(127.06,10.33) v2(127.16,80.53) v2(127.56,48.33) v2(127.51,26.86) v2(127.54,7.86) v2(128.17,86.12) v2(128.35,47.46) v2(128.43,12.71) v2(128.43,11.44) v2(129.32,43.45) v2(129.95,7.81) v2(130.84,63.9) v2(131.6,61.36) v2(131.53,51.5) v2(131.58,49.32) v2(131.98,86.12) v2(132.16,40.68) v2(132.36,80.66) v2(132.75,39.64) v2(133,67.45) v2(132.95,7.81) v2(133.13,73.55) v2(133.25,70.5) v2(133.25,12.97) v2(133.25,11.7) v2(133.51,43.19) v2(133.7,52.82) v2(133.7,51.55) v2(133.7,50.28) v2(133.89,39.64) v2(134.14,79.14) v2(134.27,77.48) v2(134.27,33.92) v2(134.23,22.15) v2(134.4,24.4) v2(134.65,29.61) v2(134.78,42.89) v2(134.78,12.97) v2(134.78,11.7) v2(134.97,52.82) v2(134.97,51.55) v2(134.97,50.28) v2(135.16,64.15) v2(135.41,80.41) v2(135.67,77.48) v2(135.79,86.12) v2(135.72,43.19) v2(135.79,21.48) v2(135.79,20.33) v2(136.24,52.82) v2(136.24,51.55) v2(136.24,50.28) v2(137.44,21.48) v2(137.44,20.33) v2(137.7,80.41) v2(137.72,48.61) v2(138.08,75.58) v2(138.08,73.67) v2(138.21,78.75) v2(138.21,70.12) v2(138.21,65.55) v2(138.21,60.34) v2(138.21,12.71) v2(138.21,11.44) v2(138.23,52.82) v2(138.26,50.23) v2(139.6,86.12) v2(139.73,12.21) v2(139.73,7.81) v2(140.24,19.32) v2(140.37,61.74) v2(140.75,21.48) v2(141,63.9) v2(141.25,80.41) v2(141.64,12.21) v2(141.76,84.72) v2(142.65,41.04) v2(143.41,86.12) v2(143.41,12.21) v2(143.54,82.44) v2(143.54,7.81) v2(144.38,41.32) v2(144.43,39.26) v2(144.43,19.29) v2(144.94,84.85) v2(146.21,79.52) v2(146.21,59.07) v2(146.46,86.12) v2(146.64,51.5) v2(146.97,55.64) v2(146.97,40.78) v2(146.97,20.72) v2(147.58,7.91) v2(147.86,61.74) v2(147.99,19.32) v2(148.11,40.78) v2(148.11,23) v2(148.87,57.42) v2(149.66,51.53) v2(149.87,84.95) v2(150.53,55.64) v2(150.91,20.72) v2(151.03,9.03) v2(151.29,61.74) v2(151.54,58.69) v2(151.67,86.12) v2(151.8,81.29) v2(152.05,48.23) v2(152.68,82.69) v2(152.94,36.59) v2(152.94,31.38) v2(153.07,84.98) v2(153.32,26.56) v2(154.59,22.75) v2(154.89,39.16) v2(155.45,84.95) v2(155.43,9.08) v2(155.86,54.42) v2(155.83,51.02) v2(155.86,49.67) v2(155.83,46.14) v2(155.99,61.1) v2(156.49,34.69) v2(156.75,27.45) v2(157.38,31.13) v2(157.99,21.89) v2(158.02,58.69) v2(158.27,44.97) v2(158.4,85.1) v2(158.53,49.67) v2(158.65,55.13) v2(158.65,8.02) v2(159.29,83.33) v2(159.67,61.86) v2(160.05,86.12) v2(160.3,19.32) v2(161.32,54.75) v2(161.32,46.12) v2(161.45,50.69) v2(161.45,8.4) v2(161.73,83.58) v2(162.46,85.36) v2(163.16,44.85) v2(163.23,81.8) v2(163.23,77.99) v2(163.23,74.18) v2(163.23,70.37) v2(163.23,66.56) v2(163.23,62.75) v2(163.23,58.94) v2(163.23,55.64) v2(163.23,51.83) v2(163.23,48.02) v2(163.23,40.4) v2(163.23,36.59) v2(163.23,32.78) v2(163.23,28.97) v2(163.23,25.16) v2(163.23,21.35) v2(163.23,17.54) v2(163.23,13.73) v2(163.23,9.92)
VDDREG_3.3V: length 3.8
  TOP w0.203: U2.45 126.56,74.37 v2(126.75,74.18) 126.54,73.97 U2.44 ; U2.37 126.04,70.53 v2(126.07,70.5)
  BOTTOM w0.305: C57.1 125.79,72.16 ; C57.1 126.31,71.64 ; C57.1 125.79,71.12
A+: length 7
  TOP w0.127: U20.16 62.65,15.01 62.51,14.87 62.51,11.02 J27.3
A-: length 6.4
  TOP w0.127: U20.2 64.42,11.82 v2(64.93,11.32)
  ART03 w0.127: J27.2 63,10.15 64.17,11.32 v2(64.93,11.32)
AC_IN0_N_C: length 8.4
  TOP w0.203: R223.1 38.74,19.27 C260.1 C253.1 38.92,16.86 R126.2 38.82,15.67 D9.1 38.82,12.15 J22.1
AC_IN0L_C: length 29.6
  TOP w0.203: J29.1 9.58,18.73 9.94,18.38 12.02,18.38 12.55,17.85 D6.1 C137.1 R117.1 v2(17.18,17.85) ; R221.1 v2(36.05,19.95)
  ART03 w0.203: v2(17.18,17.85) 24.22,17.85 26.42,20.06 35.95,20.06 v2(36.05,19.95)
AC_IN0R_C: length 40.2
  TOP w0.203: R222.1 v2(41.43,20.84) ; v2(17.11,16.46) R119.1 C138.1 13.5,16.46 D5.1 11.62,16.47 10.5,17.59 6.96,17.59 6.43,18.13 J29.3
  ART03 w0.203: v2(17.11,16.46) 24.99,16.46 27.46,18.94 39.53,18.94 v2(41.43,20.84)
AC_IN1_N: length 20
  TOP w0.203: C195.1 99.75,44.72 105.57,44.72 106.43,43.86 112.65,43.86 114.71,41.8 J18.53
AC_IN1_N_C: length 53.6
  TOP w0.203: J23.1 29.31,12.15 D7.1 C258.1 C251.1 R122.2 29.31,20.79 35.08,26.56 35.08,51.32 v2(35.97,52.21)
  ART03 w0.203: v2(44.61,52.2) 36.24,52.2 36.23,52.21 v2(35.97,52.21)
  BOTTOM w0.203: J19.53 v2(44.61,52.2)
AC_IN1_P: length 19.7
  TOP w0.203: C194.1 99.62,45.86 106.08,45.86 106.96,44.97 113.31,44.97 114.89,43.4 J18.49
AC_IN1_P_C: length 51
  TOP w0.203: v2(36.1,49.8) 36.1,26.05 30.54,20.49 R121.1 30.44,16.81 C252.1 C257.1 D8.1 30.44,12.15 J23.2
  ART03 w0.203: v2(36.1,49.8) 43.81,49.8 v2(44.61,50.6)
  BOTTOM w0.203: J19.49 v2(44.61,50.6)
AC_INO_P_C: length 8.4
  TOP w0.203: J22.2 37.69,12.15 D10.1 37.69,15.67 R125.1 37.6,16.98 C254.1 C259.1 37.65,19.27 R220.1
AC_MICBIAS0: length 11.8
  TOP w0.203: U3.W22 95.35,45.89 96.32,45.89 96.63,45.58 96.89,45.58 97.96,44.52 98.13,44.52 C190.2 98.68,43.6 98.84,43.45 R95.1 R209.1 R208.1
AC_MICBIAS0_DIF: length 15
  TOP w0.203: R95.2 104.93,43.45 105.82,42.56 112.43,42.56 114.79,40.2 J18.57
AC_MICBIAS0_DIF_C: length 59
  TOP w0.203: R124.2 v2(34.83,18.05) 34.83,21.73 38.13,25.03 v2(38.13,53.48) ; C98.1 C256.1 v2(24.91,14.99)
  ART03 w0.203: v2(34.83,18.05) 34.73,17.95 29.19,17.95 26.23,14.99 v2(24.91,14.99) ; v2(38.13,53.48) 38.44,53.8 v2(44.61,53.8)
  BOTTOM w0.203: J19.57 v2(44.61,53.8)
AC_MICBIAS0_L: length 15.2
  TOP w0.203: J18.65 114.69,37 111.16,40.53 104.65,40.53 R208.2
AC_MICBIAS0_L_C: length 56.1
  TOP w0.203: R116.2 C97.1 24.67,19.32 33.05,27.7 33.05,53.83 34.71,55.49 v2(34.73,55.49)
  ART03 w0.203: v2(34.73,55.49) 35.13,55.89 43.21,55.89 44.31,57 v2(44.61,57)
  BOTTOM w0.203: J19.65 v2(44.61,57)
AC_MICBIAS0_R: length 15.1
  TOP w0.203: J18.61 114.74,38.6 111.79,41.54 105.03,41.54 R209.2
AC_MICBIAS0_R_C: length 57.7
  TOP w0.203: v2(36.23,54.12) 34.07,51.96 34.07,27.07 24.92,17.92 22.89,17.92 21.37,16.4 C96.1 R118.1
  ART03 w0.203: v2(36.23,54.12) 36.99,54.88 43.59,54.88 44.11,55.4 v2(44.61,55.4)
  BOTTOM w0.203: J19.61 v2(44.61,55.4)
AC_MICBIAS1: length 29.4
  TOP w0.127: 96.13,45.48 96.04,45.57 95.22,45.57 95.19,45.6 94.99,45.6 U3.W21
  TOP w0.203: J18.69 114.64,35.4 110.75,39.28 102.11,39.28 101.76,39.64 101.76,41.29 100.61,42.43 98.84,42.43 98.68,42.59 C193.2 98.33,42.94 97.69,43.58 97.69,44.28 96.8,45.18 96.44,45.18 96.13,45.48
AC_MICBIAS1_C: length 50
  TOP w0.203: R120.2 C255.1 C95.1 33.48,21.91 37.11,25.54 37.11,56.66 v2(36.73,57.04)
  ART03 w0.203: v2(44.65,58.6) 43.73,57.67 37.37,57.67 v2(36.73,57.04)
  BOTTOM w0.203: J19.69 v2(44.65,58.6)
AC_MICIN0_L/DIFFIN0_P: length 22.8
  TOP w0.203: J18.73 118.16,33.8 114.71,33.8 110.32,38.19 101.86,38.19 100.61,39.44 100.61,40.81 C191.1
AC_MICIN0_L/DIFFIN0_P_C: length 45.7
  TOP w0.203: v2(39.15,58.56) 39.15,24.4 37.52,22.77 R220.2 R221.2
  ART03 w0.203: v2(39.15,58.56) 39.27,58.69 43.1,58.69 v2(44.61,60.2)
  BOTTOM w0.203: J19.73 v2(44.61,60.2)
AC_MICIN0_R/DIFFIN0_N: length 23.6
  TOP w0.203: C192.1 99.5,38.72 101.2,37.02 109.83,37.02 114.66,32.2 J18.77
AC_MICIN0_R/DIFFIN0_N_C: length 45.8
  TOP w0.203: v2(40.16,59.58) 40.16,23.76 38.87,22.47 R223.2 R222.2
  ART03 w0.203: v2(40.16,59.58) 42.39,59.58 v2(44.61,61.8)
  BOTTOM w0.203: J19.77 v2(44.61,61.8)
AC_OUTL: length 31.5
  TOP w0.203: J18.70 v2(121.37,35.4) ; v1(96.05,43.25) 96.05,43.25 96.09,43.3 96.09,43.84 U3.AA22
  ART03 w0.203: v2(121.37,35.4) 117.99,35.4 112.88,40.5 99.44,40.5 96.69,43.25 v1(96.05,43.25)
AC_OUTL/AC_OUTR: length 1.4
  TOP w0.127: R228.2 C139.1
AC_OUTL_C: length 34.6
  TOP w0.203: R226.2 27.22,40.16 28.99,41.92 v2(28.99,57.16)
  ART03 w0.203: v2(28.99,57.16) 30.26,57.16 32.67,59.58 v2(38.89,59.58)
  BOTTOM w0.203: v2(38.89,59.58) 39.15,59.58 40.13,58.6 J19.70
AC_OUTL_PAM8303D: length 20.5
  TOP w0.203: R228.1 27.97,59.34 27.97,42.94 26.66,41.63 R225.1
AC_OUTL_SGM8903: length 2.7
  TOP w0.203: C126.2 R107.2 R226.1
AC_OUTR: length 33.4
  TOP w0.127: U3.AA21 95,44.29 95,43.47 v1(95.23,43.25)
  TOP w0.203: J18.74 v2(121.37,33.8)
  ART03 w0.203: v1(95.23,43.25) 95.23,42.36 98.28,39.31 112.43,39.31 117.94,33.8 121.37,33.8 v2(121.37,33.8)
AC_OUTR_C: length 45.6
  TOP w0.203: v2(40.8,60.59) 37.88,60.59 32.03,54.75 32.03,28.08 30.03,26.08 R224.2
  BOTTOM w0.203: v2(40.8,60.59) 41.2,60.2 J19.74
AC_OUTR_PAM8303D: length 38.7
  TOP w0.203: R224.1 28.07,27.55 30,29.48 30,61.61 29.06,62.55 R229.1
AC_OUTR_SGM8903: length 2.7
  TOP w0.203: R227.1 R106.2 C125.1
AN0: length 4.5
  TOP w0.127: R144.2 116.62,73.32 118.58,73.32 118.67,73.41 R1002.2 118.84,73.97 U2.17
AN1: length 7.2
  TOP w0.127: R145.2 114.29,71.84 116.02,71.84 116.39,72.21 R1003.2 116.79,72.94 118.74,72.94 119.37,73.57 U2.18
B+: length 7
  TOP w0.127: U20.5 66.69,15.01 66.96,14.75 66.96,10.74 J27.4
B-: length 6.7
  TOP w0.127: U20.3 64.92,12.34 v2(64.93,12.33)
  ART03 w0.127: J27.1 61.75,9.92 64.17,12.33 v2(64.93,12.33)
CEC_A_SII9022A: length 18.9
  TOP w0.127: v2(145.32,48.4) 145.29,48.38 R6.1 ; R6.1 145.29,44.46 145.61,44.15 U17.3 ; R6.1 R219.2 ; U22.71 v2(143.41,55.3)
  ART03 w0.127: v2(143.41,55.3) 145.32,53.4 v2(145.32,48.4)
DAMP+: length 9.7
  BOTTOM w0.127: J26.3 63.7,84.98 66.45,84.98 66.83,84.6 R167.1 LB13.2
DAMP-: length 8.6
  BOTTOM w0.127: J26.4 62.83,85.36 66.83,85.36 67.34,84.85 R168.1 LB14.2
DC_IRIS_PWM: length 118.8
  TOP w0.127: v2(55.02,51.45) 55.02,44.08 53.24,42.31 53.24,38.88 56.95,35.17 85.6,35.17 90.25,39.82 90.25,42.05 90.53,42.33 90.53,43.58 90.45,43.66 90.45,44.93 U3.Y14
  ART03 w0.127: v2(87.15,84.22) 87.15,81.75 83.01,77.61 72.39,77.61 68.1,73.32 68.1,58.69 66.96,57.55 56.67,57.55 55.15,56.02 55.15,51.58 v2(55.02,51.45)
  BOTTOM w0.127: R2.1 v2(87.15,84.22)
DDR3_A0: length 25.3
  TOP w0.127: U3.H4 v1(83.3,53.39) ; v1(75.39,67.87) 75.57,67.87 76.7,69 U14.N3
  ART03 w0.127: v1(75.39,67.87) 75.01,67.49 75.01,66.64 75.33,66.32 75.33,57.82 79.29,53.86 79.68,53.86 80.55,53 82.91,53 v1(83.3,53.39)
  BOTTOM w0.127: U15.N3 76.7,66.03 75.77,66.97 75.77,67.49 v1(75.39,67.87)
DDR3_A1: length 23.2
  TOP w0.127: U3.F3 v1(83.3,54.04) ; U14.P7 75.9,66.22 75.41,66.72 75.04,66.72 v1(74.62,67.13)
  ART04 w0.127: v1(74.62,67.13) 74.62,66.44 75.09,65.98 75.09,63.25 75.71,62.63 75.71,58.91 79.46,55.16 79.46,55.16 79.92,54.69 82.65,54.69 v1(83.3,54.04)
  BOTTOM w0.127: v1(74.62,67.13) 75.01,67.51 75.01,68.12 75.9,69.01 U15.P7
DDR3_A2: length 27.7
  TOP w0.127: U3.H2 81.99,52.73 81.34,52.73 v1(80.7,52.09) ; v1(73.86,67.9) 74.48,68.52 75.37,68.52 75.46,68.52 75.9,68.96 U14.P3
  ART03 w0.127: v1(73.86,67.9) 73.48,67.51 73.48,66.87 73.42,66.81 73.42,58.11 78.68,52.86 79.4,52.86 80.16,52.09 v1(80.7,52.09)
  BOTTOM w0.127: U15.P3 75.9,66.07 75.33,66.64 74.54,66.64 74.24,66.94 74.24,67.51 v1(73.86,67.9)
DDR3_A3: length 23.1
  TOP w0.127: U14.N2 76.32,69.53 76.32,69 75.6,68.28 75.15,68.28 75.01,68.13 75.01,67.51 v1(75.39,67.13) ; U3.D2 v1(82,55.34)
  ART04 w0.127: v1(82,55.34) 81.62,54.96 80.2,54.96 76.89,58.27 76.89,60.26 76.09,61.06 76.09,62.79 75.52,63.36 75.52,67 v1(75.39,67.13)
  BOTTOM w0.127: v1(75.39,67.13) 75.39,66.97 76.32,66.03 76.32,65.5 U15.N2
DDR3_A4: length 28.9
  TOP w0.127: v1(74.62,67.9) 74.24,67.51 74.24,66.94 74.82,66.36 75.23,66.36 75.51,66.08 75.51,65.51 U14.P8 ; U3.K4 v1(83.95,52.09)
  ART03 w0.127: v1(83.95,52.09) 83.29,52.75 80.4,52.75 79.65,53.49 79.12,53.49 74.95,57.66 74.95,65.76 74.24,66.47 74.24,67.51 v1(74.62,67.9)
  BOTTOM w0.127: v1(74.62,67.9) 74.62,68.12 75.49,68.99 75.49,69.51 U15.P8
DDR3_A5: length 29.5
  TOP w0.127: U3.J4 v1(83.3,52.09) ; v1(73.86,67.13) 73.48,67.51 73.48,68.17 74.07,68.76 75.27,68.76 75.49,68.99 75.49,69.51 U14.P2
  ART03 w0.127: v1(83.3,52.09) 82.92,52.47 80.29,52.47 79.58,53.18 78.9,53.18 73.8,58.27 73.8,67.08 v1(73.86,67.13)
  BOTTOM w0.127: U15.P2 75.51,65.51 75.51,66.08 75.23,66.36 74.16,66.36 73.86,66.66 v1(73.86,67.13)
DDR3_A6: length 30
  TOP w0.127: U3.G2 v1(82,53.39) ; U14.R8 74.7,65.52 73.19,65.52 v1(71.58,67.13)
  ART04 w0.127: v1(71.58,67.13) 71.58,66.49 72.88,65.19 72.88,62.77 73.6,62.05 73.6,58.76 79.35,53.01 81.62,53.01 v1(82,53.39)
  BOTTOM w0.127: v1(71.58,67.13) 71.96,67.51 71.96,68.09 73.37,69.51 74.7,69.51 U15.R8
DDR3_A7: length 36.1
  TOP w0.127: v1(70.81,67.9) 70.81,68.3 72.83,70.31 74.7,70.31 U14.R2 ; U3.J3 v1(82.65,52.09)
  ART04 w0.127: v1(70.81,67.9) 70.39,67.47 70.39,66.18 71.94,64.63 71.94,59.32 78.79,52.47 82.27,52.47 v1(82.65,52.09)
  BOTTOM w0.127: v1(70.81,67.9) 70.43,67.51 70.43,66.97 72.67,64.73 74.71,64.73 U15.R2
DDR3_A8: length 28.9
  TOP w0.127: U14.T8 73.02,65.11 71.2,66.94 71.2,67.31 71.58,67.69 v1(71.58,67.9) ; v1(80.7,53.39) 81.08,53.01 81.62,53.01 U3.H1
  ART04 w0.127: v1(80.7,53.39) 80.4,53.69 79.21,53.69 73.98,58.92 73.98,62.21 73.23,62.96 73.23,65.37 71.96,66.64 71.96,67.51 v1(71.58,67.9)
  BOTTOM w0.127: U15.T8 73.24,69.92 71.58,68.25 v1(71.58,67.9)
DDR3_A9: length 31.3
  TOP w0.127: v1(72.34,67.13) 71.96,67.51 71.96,68.07 73.4,69.51 74.7,69.51 75.09,69.11 U14.R3 ; U3.J2 v1(82,52.09)
  ART03 w0.127: v1(72.34,67.13) 72.09,66.89 72.09,58.37 78.25,52.2 79.29,52.2 80.02,51.47 81.38,51.47 v1(82,52.09)
  BOTTOM w0.127: v1(72.34,67.13) 72.34,66.56 73.38,65.52 74.71,65.52 U15.R3
DDR3_A10: length 20.5
  TOP w0.127: v1(77.67,67.13) 77.67,66.54 U14.L7 ; U3.E3 v1(82.65,55.34)
  ART03 w0.127: v1(82.65,55.34) 82.54,55.34 82.16,54.96 80.47,54.96 77.52,57.91 77.52,61.15 78.16,61.79 78.16,63 77.52,63.64 77.52,65.78 77.67,65.93 v1(77.67,67.13)
  BOTTOM w0.127: v1(77.67,67.13) 78.05,67.51 78.05,68.87 U15.L7
DDR3_A11: length 23.8
  TOP w0.127: v1(73.1,67.13) 73.95,66.28 74.52,66.28 74.89,65.92 U14.R7 ; U3.F1 v1(81.35,54.04)
  ART04 w0.127: v1(81.35,54.04) 79.46,54.04 74.95,58.55 74.95,62.31 73.67,63.6 73.67,65.57 73.1,66.14 v1(73.1,67.13)
  BOTTOM w0.127: v1(73.1,67.13) 73.48,67.51 73.48,68.19 73.85,68.56 74.55,68.56 U15.R7
DDR3_A12: length 21.3
  TOP w0.127: U14.N7 76.7,66.58 v1(76.15,67.13) ; U3.G3 v1(82.65,54.04)
  ART03 w0.127: v1(76.15,67.13) 76.73,66.56 76.73,57.62 79.9,54.45 80.79,54.45 80.8,54.44 82.25,54.44 v1(82.65,54.04)
  BOTTOM w0.127: v1(76.15,67.13) 76.53,67.51 76.53,68.23 76.7,68.41 U15.N7
DDR3_A13: length 27.6
  TOP w0.127: U14.T3 73.56,69.11 v1(72.34,67.9) ; U3.J1 v1(81.35,52.09)
  ART03 w0.127: v1(81.35,52.09) 80.97,51.71 80.16,51.71 79.34,52.54 78.46,52.54 72.47,58.52 72.47,66.57 72.72,66.82 72.72,67.51 v1(72.34,67.9)
  BOTTOM w0.127: v1(72.34,67.9) 72.72,67.51 72.72,66.81 73.62,65.92 U15.T3
DDR3_A14: length 24.5
  TOP w0.127: v1(73.1,67.9) 72.72,67.51 72.72,66.81 73.62,65.92 U14.T7 ; U3.F2 v1(82,54.04)
  ART04 w0.127: v1(82,54.04) 81.62,54.42 79.66,54.42 75.33,58.75 75.33,62.47 74.68,63.12 74.68,65.62 73.48,66.82 73.48,67.51 v1(73.1,67.9)
  BOTTOM w0.127: U15.T7 73.56,69.11 73.1,68.65 v1(73.1,67.9)
DDR3_A15: length 22.7
  TOP w0.127: U14.M7 77.29,66.13 77.29,67.51 v1(77.67,67.9) ; U3.F4 v1(83.95,54.04)
  ART03 w0.127: v1(77.67,67.9) 77.29,67.51 77.29,66.31 77.14,66.16 77.14,57.75 80.2,54.69 83.29,54.69 v1(83.95,54.04)
  BOTTOM w0.127: U15.M7 77.5,68.07 v1(77.67,67.9)
DDR3_BA0: length 19.3
  TOP w0.127: U3.C1 81.62,56.37 80.45,56.37 v1(80.29,56.53) ; U14.M2 77.13,69.55 77.13,69 76.53,68.4 76.53,67.51 v1(76.91,67.13)
  ART04 w0.127: v1(80.29,56.53) 79.94,56.53 77.73,58.75 77.73,60.5 76.91,61.32 v1(76.91,67.13)
  BOTTOM w0.127: U15.M2 77.13,65.48 77.13,66.18 76.91,66.4 v1(76.91,67.13)
DDR3_BA1: length 24
  TOP w0.127: U3.G1 v1(81.35,53.39) ; U14.N8 76.32,65.5 76.32,66.33 75.77,66.89 75.77,67.51 v1(76.15,67.9)
  ART03 w0.127: v1(81.35,53.39) 80.57,54.17 79.64,54.17 75.71,58.1 75.71,62.71 76.28,63.29 76.28,66.13 75.77,66.64 75.77,67.51 v1(76.15,67.9)
  BOTTOM w0.127: U15.N8 76.32,69.53 76.32,68.62 76.15,68.45 v1(76.15,67.9)
DDR3_BA2: length 19.4
  TOP w0.127: U3.E1 v1(81.35,55.34) ; U14.M3 77.5,68.84 76.91,68.25 v1(76.91,67.9)
  ART04 w0.127: v1(81.35,55.34) 80.95,55.73 79.97,55.73 77.32,58.38 77.32,60.37 76.53,61.16 76.53,67.51 v1(76.91,67.9)
  BOTTOM w0.127: v1(76.91,67.9) 77.29,67.51 77.29,66.51 77.5,66.3 U15.M3
DDR3_CAS_N: length 17.3
  TOP w0.127: v1(79.2,67.9) 79.1,67.99 U14.K3 ; U3.D1 v1(81.35,55.99)
  ART03 w0.127: v1(81.35,55.99) 81.35,56.03 79.74,57.64 79.74,63.26 78.68,64.32 78.68,66.65 78.82,66.79 78.82,67.51 v1(79.2,67.9)
  BOTTOM w0.127: U15.K3 79.1,66.47 79.58,66.95 79.58,67.32 79.2,67.7 v1(79.2,67.9)
DDR3_CKE: length 20.8
  TOP w0.127: U14.K9 79.1,64.61 78.71,65.01 78.71,66.08 79.76,67.13 v1(79.96,67.13) ; U3.C3 82.65,56.64 81.35,56.64 80.93,57.06 80.93,57.98 v1(81.01,58.05)
  ART04 w0.127: v1(81.01,58.05) 81.01,60.21 80.52,60.7 80.52,63.39 79.92,63.99 79.92,67.1 v1(79.96,67.13)
  BOTTOM w0.127: U15.K9 79.1,70.46 78.73,70.09 78.73,68.9 79.58,68.06 79.58,67.7 79.96,67.32 v1(79.96,67.13)
DDR3_CLK_N: length 21.3
  TOP w0.102: U3.B1 v1(81.35,57.29)
  TOP w0.109: v1(78.85,72.35) 79.06,72.56 79.06,73.23 R7.1 ; U14.K7 v1(79.5,66.31)
  ART03 w0.102: v1(78.85,72.35) 79.02,72.17 79.02,70.98 78.54,70.5 78.54,69.27 78.92,68.89 79.33,68.89 v1(79.5,68.72) 79.75,68.96 79.88,68.96 80.33,68.51 80.33,66.86 80.08,66.61 79.66,66.61 79.5,66.46 v1(79.5,66.31) 79.75,66.06 79.75,65.92 79.63,65.79 79.63,65.15 80.75,64.02 80.75,60.86 81.4,60.21 81.4,57.97 81.54,57.83 81.54,57.48 v1(81.35,57.29)
  BOTTOM w0.109: U15.K7 v1(79.5,68.72)
DDR3_CLK_P: length 21
  TOP w0.102: U3.B2 v1(82,57.29)
  TOP w0.109: U14.J7 v1(80.3,66.31) ; v1(79.51,72.35) 79.35,72.51 79.35,73.08 R7.2
  ART03 w0.102: v1(82,57.29) 81.84,57.44 81.84,57.95 81.7,58.09 81.7,60.34 81.06,60.99 81.06,64.15 79.93,65.27 79.93,65.67 80.06,65.79 80.06,66.07 v1(80.3,66.31) 80.3,66.4 80.63,66.73 80.63,68.64 80,69.27 79.75,69.27 v1(79.5,69.51) 79.18,69.19 79.05,69.19 78.85,69.39 78.85,70.37 79.33,70.85 79.33,72.17 v1(79.51,72.35)
  BOTTOM w0.109: U15.J7 v1(79.5,69.51)
DDR3_CS_N: length 20.4
  TOP w0.127: U3.E2 82,54.69 81.35,54.69 v1(80.7,55.34) ; U14.L2 77.93,69.55 77.93,68.87 78.05,68.75 78.05,67.51 v1(78.43,67.13)
  ART03 w0.127: v1(78.43,67.13) 78.28,66.98 78.28,64.16 78.54,63.9 78.54,60.66 78.71,60.49 78.71,57.32 v1(80.7,55.34)
  BOTTOM w0.127: U15.L2 77.92,65.5 77.92,66.62 v1(78.43,67.13)
DDR3_DM0: length 14.3
  TOP w0.127: U3.D10 v1(87.2,55.34) ; U14.E7 v1(83.5,65.51)
  ART03 w0.127: v1(87.2,55.34) 87.61,55.75 87.61,58.82 86.61,59.82 86.61,62.46 85.83,63.24 85.83,64.69 85.58,64.96 85.42,65.12 85.42,65.12 84.64,65.9 83.88,65.9 v1(83.5,65.51)
DDR3_DM1: length 17.3
  TOP w0.127: U14.D3 v1(83.5,68.72) ; U3.C15 v1(90.45,56.64)
  ART03 w0.127: v1(83.5,68.72) 83.88,68.33 85.25,68.33 85.76,67.83 86.64,67.83 89.52,64.96 89.52,58.66 90.45,57.73 v1(90.45,56.64)
DDR3_DM2: length 16.3
  TOP w0.127: U3.D5 v1(84.6,55.99)
  ART04 w0.127: v1(82.7,69.51) 81.52,68.33 81.52,63.51 82.75,62.29 82.75,60.12 83.72,59.15 83.72,56.87 v1(84.6,55.99)
  BOTTOM w0.127: U15.E7 v1(82.7,69.51)
DDR3_DM3: length 11.9
  TOP w0.127: v1(86.55,56.64) 86.22,56.32 U3.C8
  ART04 w0.127: v1(86.55,56.64) 86.17,57.02 86.17,59.04 84.91,60.3 84.91,62.43 84.38,62.96 84.38,64.1 84.68,64.4 84.68,65.93 v1(84.3,66.32)
  BOTTOM w0.127: v1(84.3,66.32) U15.D3
DDR3_DQ0: length 20.1
  TOP w0.127: U14.E3 v1(83.5,69.51) ; U3.D14 v1(90.45,55.34)
  ART03 w0.127: v1(90.45,55.34) 91.09,55.98 91.09,58.1 90.28,58.91 90.28,65.28 86.43,69.12 83.9,69.12 v1(83.5,69.51)
DDR3_DQ1: length 15.8
  TOP w0.127: U3.D11 v1(88.5,55.99) ; U14.F7 v1(82.7,66.32)
  ART03 w0.127: v1(88.5,55.99) 87.99,56.5 87.99,58.97 86.99,59.98 86.99,62.69 86.28,63.39 86.28,65.67 86.06,65.9 85.26,65.9 84.46,66.7 83.08,66.7 v1(82.7,66.32)
DDR3_DQ2: length 20.7
  TOP w0.127: v1(81.9,69.51) 82.3,69.91 U14.F2 ; U3.D12 v1(89.15,55.34)
  ART03 w0.127: v1(89.15,55.34) 89.91,56.09 89.91,56.95 89.14,57.72 89.14,64.77 86.45,67.45 85.63,67.45 85.12,67.96 82.77,67.96 81.9,68.83 v1(81.9,69.51)
DDR3_DQ3: length 12.8
  TOP w0.127: U14.F8 82.71,64.71 82.71,60.42 83.29,59.83 86.99,59.83 87.85,58.97 87.85,57.29 U3.B10
DDR3_DQ4: length 19.5
  TOP w0.127: v1(81.1,68.71) U14.H3 ; U3.D13 v1(89.15,55.99)
  ART03 w0.127: v1(89.15,55.99) 89.53,56.37 89.53,56.8 88.75,57.57 88.75,64.61 86.29,67.07 85.63,67.07 85.15,67.55 82.62,67.55 81.46,68.71 v1(81.1,68.71)
DDR3_DQ5: length 12.6
  TOP w0.127: U14.H8 81.12,64.7 81.12,63.71 82.33,62.5 82.33,60.24 83.11,59.45 86.83,59.45 87.58,58.71 87.58,57.67 U3.A10
DDR3_DQ6: length 23.5
  TOP w0.127: U14.G2 81.12,70.3 81.12,71.2 81.69,71.77 84.74,71.77 85.12,71.39 85.12,70.5 85.33,70.29 87.11,70.29 91.72,65.68 91.72,57.91 U3.A16
DDR3_DQ7: length 18.5
  TOP w0.127: v1(81.9,66.32) 81.51,66.71 80.93,66.71 80.7,66.48 U14.H7 ; U3.C12 v1(89.15,56.64)
  ART03 w0.127: v1(81.9,66.32) 82.65,67.06 84.56,67.06 84.93,66.7 86.13,66.7 88.37,64.45 88.37,57.42 v1(89.15,56.64)
DDR3_DQ8: length 16.8
  TOP w0.127: U3.C13 89.8,56.65 89.8,57.78 89.9,57.88 89.9,58.31 89.67,58.54 89.67,64.83 86.95,67.55 84.77,67.55 83.9,66.69 U14.D7
DDR3_DQ9: length 17.8
  TOP w0.127: U3.C14 v1(90.45,55.99) ; v1(84.3,68.71) U14.C3
  ART03 w0.127: v1(84.3,68.71) 85.36,68.71 85.86,68.21 86.8,68.21 89.9,65.12 89.9,58.79 90.83,57.86 90.83,56.37 v1(90.45,55.99)
DDR3_DQ10: length 12.3
  TOP w0.127: U14.C8 v1(84.3,65.51) ; U3.D9 v1(86.55,55.34)
  ART03 w0.127: v1(86.55,55.34) 86.17,55.72 86.17,57.42 86.17,57.45 86.39,57.67 86.39,59.1 85.1,60.4 85.1,62.52 84.69,62.93 84.69,65.13 v1(84.3,65.51)
DDR3_DQ11: length 19.1
  TOP w0.127: U3.D15 v1(91.1,55.34) ; v1(85.1,69.51) 84.7,69.91 84.7,69.91 U14.C2
  ART03 w0.127: v1(91.1,55.34) 91.37,55.61 91.37,58.36 90.66,59.07 90.66,65.43 86.2,69.9 85.48,69.9 v1(85.1,69.51)
DDR3_DQ12: length 10
  TOP w0.127: U3.B11 88.5,57.29 88.5,59.53 88.3,59.73 88.3,61.99 87.79,62.5 87.79,64.43 U14.A7
DDR3_DQ13: length 15.6
  TOP w0.127: U3.B15 91.1,57.29 91.1,57.8 91.33,58.03 91.33,65.52 86.94,69.92 U14.A2
DDR3_DQ14: length 9.9
  TOP w0.127: U3.A11 88.17,59.19 87.15,60.21 85.63,60.21 85.43,60.42 85.43,62.8 85.88,63.26 85.88,64.73 U14.B8
DDR3_DQ15: length 14
  TOP w0.127: U14.A3 87.21,69.11 90.95,65.37 90.95,58.28 90.77,58.1 U3.A15
DDR3_DQ16: length 12.6
  TOP w0.127: v1(86.55,55.99) 86.22,55.66 U3.D8
  ART04 w0.127: v1(83.5,66.32) 83.88,65.93 83.88,62.92 84.53,62.27 84.53,60.14 85.91,58.76 85.91,56.63 v1(86.55,55.99)
  BOTTOM w0.127: U15.E3 v1(83.5,66.32)
DDR3_DQ17: length 15.8
  TOP w0.127: U3.D6 v1(85.25,55.34)
  ART04 w0.127: v1(82.7,68.71) 82.7,67.71 83.09,67.32 83.09,64.3 83.51,63.88 83.51,60.51 85.63,58.38 85.63,55.72 v1(85.25,55.34)
  BOTTOM w0.127: U15.F7 v1(82.7,68.71)
DDR3_DQ18: length 8.1
  TOP w0.127: v1(82.86,58.48) 82.86,57.73 U3.A3
  BOTTOM w0.127: U15.F2 82.32,65.11 82.74,64.69 82.74,63.86 83.22,63.39 83.22,58.84 v1(82.86,58.48)
